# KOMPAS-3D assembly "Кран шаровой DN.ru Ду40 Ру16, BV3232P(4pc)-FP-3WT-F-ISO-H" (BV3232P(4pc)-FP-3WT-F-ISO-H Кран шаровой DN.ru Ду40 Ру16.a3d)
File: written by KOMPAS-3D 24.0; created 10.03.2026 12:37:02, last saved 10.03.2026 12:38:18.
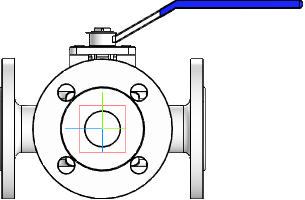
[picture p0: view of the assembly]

Document properties: Автор: R2D2; Полное имя файла: E:\Работа\Зайцев\BV3232P(4pc)-FP-3WT-F-ISO-H Кран шаровой DN.ru Ду15-100 Ру16\DN40\исходные материалы\BV3232P(4pc)-FP-3WT-F-ISO-H Кран шаровой DN.ru Ду40 Ру16.a3d

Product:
- Component [assembly]: Сборка1  | qty 1  | pos. 1  | Масса: 13.980546; Автор: R2D2; source file: dn40_3d_step.a3d
- Part/product: Кран шаровой DN.ru Ду40 Ру16  | designation BV3232P(4pc)-FP-3WT-F-ISO-H
    Масса: 11.65
    Раздел спецификации: Прочие изделия
    Примечание: D160-36350

Referenced files in E:\Работа\Зайцев\BV3232P(4pc)-FP-3WT-F-ISO-H Кран шаровой DN.ru Ду15-100 Ру16\DN40\исходные материалы\: dn40_3d_step.a3d
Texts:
  BV3232P(4pc)-FP-3WT-F-ISO-H
  Сборка1 Сборка1
  Ось Z.Начало координат
  Ось Y.Начало координат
